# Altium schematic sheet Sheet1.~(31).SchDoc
size A
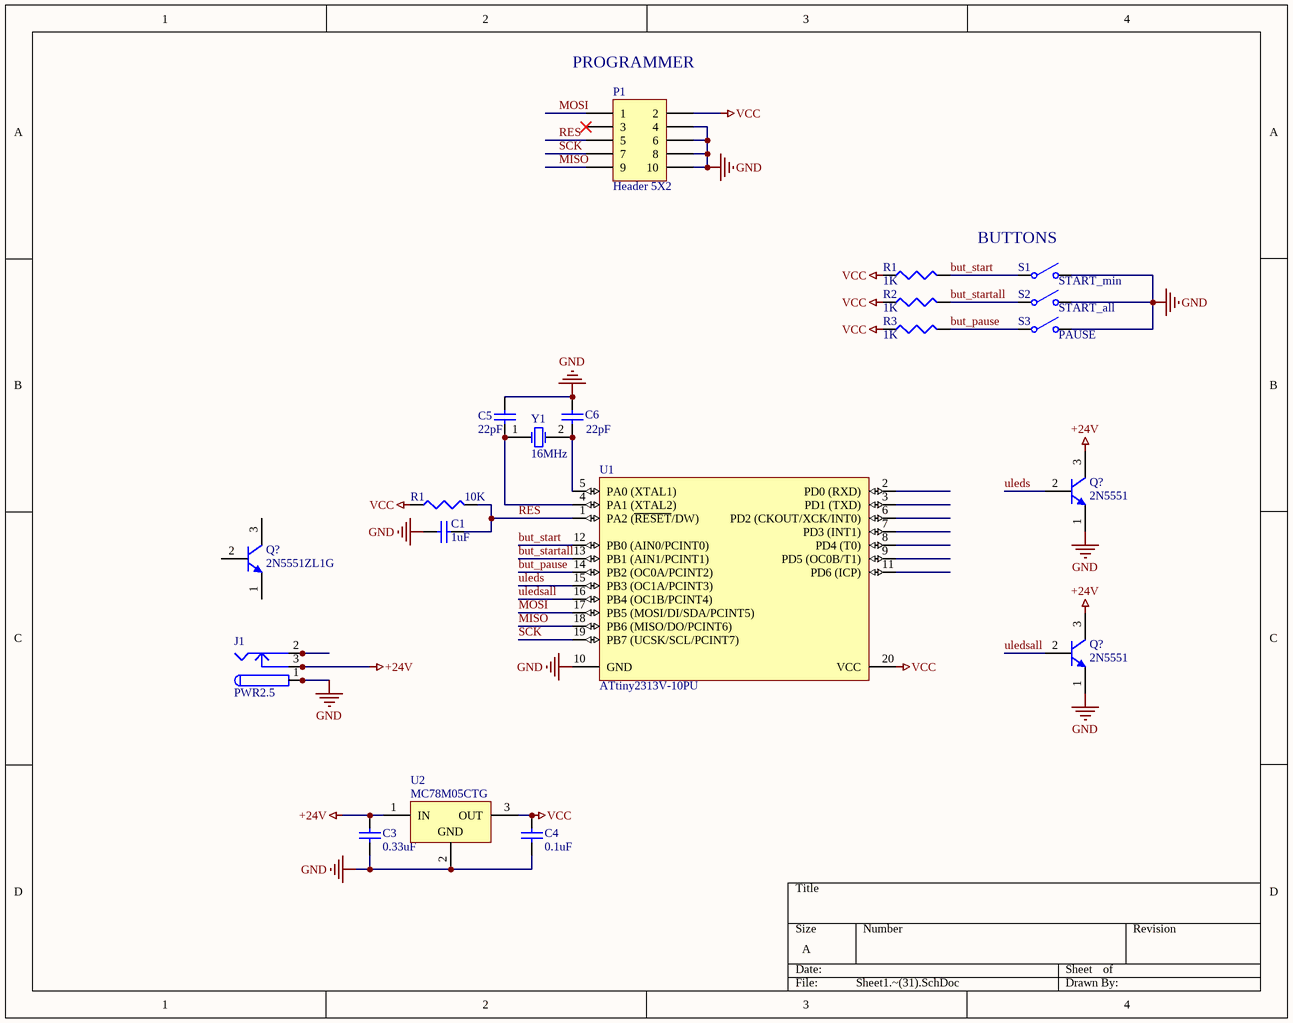
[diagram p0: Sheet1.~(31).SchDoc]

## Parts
(Parts that share a designator on the sheet are numbered #1, #2 ... from top to bottom, then left to right.)
C1  value 1uF  [1608[0603]]  (hidden comment: Cap Semi)
C3  value 0.33uF  [1608[0603]]  (hidden comment: Cap Semi)
C4  value 0.1uF  [1608[0603]]  (hidden comment: Cap Semi)
C5  value 22pF  [1608[0603]]  (hidden comment: Cap Semi)
C6  value 22pF  [1608[0603]]  (hidden comment: Cap Semi)
J1  PWR2.5  [KLD-0202]
P1  Header 5X2  [HDR2X5]
Q?#1  2N5551  [ONSC-TO-92-3-29-11_AM_BL]
Q?#2  2N5551ZL1G  [ONSC-TO-92-3-29-11_AM_BL]
Q?#3  2N5551  [ONSC-TO-92-3-29-11_AM_BL]
R1#1  value 1K  [J1-0603]  (hidden comment: Res3)
R1#2  value 10K  [J1-0603]  (hidden comment: Res3)
R2  value 1K  [J1-0603]  (hidden comment: Res3)
R3  value 1K  [J1-0603]  (hidden comment: Res3)
S1  START_min  [SPST-2]
S2  START_all  [SPST-2]
S3  PAUSE  [SPST-2]
U1  ATtiny2313V-10PU  [20P3]
U2  MC78M05CTG  [TO220]
Y1  16MHz  [HC-49U]

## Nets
+24V: C3.2 J1.3 J1.3A J1.3B Q?#1.3(C) Q?#3.3(C) U2.1(IN)
GND: C1.2 C3.1 C4.1 C5.1 C6.1 J1.1 J1.1A J1.1B P1.4 P1.6 P1.8 P1.10 Q?#1.1(E) Q?#3.1(E) S1.2(NO) S2.2(NO) S3.2(NO) U1.10(GND) U2.2(GND)
VCC: C4.2 P1.2 R1#1.1 R1#2.1 R2.1 R3.1 U1.20(VCC) U2.3(OUT)
but_pause: R3.2 S3.1(COMMON) U1.14(PB2_(OC0A/PCINT2))
but_start: R1#1.2 S1.1(COMMON) U1.12(PB0_(AIN0/PCINT0))
but_startall: R2.2 S2.1(COMMON) U1.13(PB1_(AIN1/PCINT1))
MISO: P1.9 U1.18(PB6_(MISO/DO/PCINT6))
MOSI: P1.1 U1.17(PB5_(MOSI/DI/SDA/PCINT5))
RES: C1.1 P1.5 R1#2.2 U1.1(PA2_(~{RESET}/DW))
SCK: P1.7 U1.19(PB7_(UCSK/SCL/PCINT7))
uleds: Q?#1.2(B) U1.15(PB3_(OC1A/PCINT3))
uledsall: Q?#3.2(B) U1.16(PB4_(OC1B/PCINT4))
NetC5_2: C5.2 U1.4(PA1_(XTAL2)) Y1.1(OSC1)
NetC6_2: C6.2 U1.5(PA0_(XTAL1)) Y1.2(OSC2)
NetJ1_2: J1.2 J1.2A J1.2B

Not connected (* = marked no-connect by the designer): P1 3*; Q?#2 1(E) 2(B) 3(C); U1 2(PD0_(RXD)) 3(PD1_(TXD)) 6(PD2_(CKOUT/XCK/INT0)) 7(PD3_(INT1)) 8(PD4_(T0)) 9(PD5_(OC0B/T1)) 11(PD6_(ICP))

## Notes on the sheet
- (near P1) PROGRAMMER
- (near S1) BUTTONS

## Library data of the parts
C1 C3-C6 = Cap Semi: Capacitor (Semiconductor SIM Model)
J1 = PWR2.5: Low Voltage Power Supply Connector
P1 = Header 5X2: Header, 5-Pin, Dual row
Q?#1 Q?#3 = CMP-1048-01479-1: Amplifier Transistor, NPN Silicon, 3-Pin TO-92, Pb-Free, Tape and Reel; PartNumber: 2N5551RL1G; Manufacturer: On Semiconductor; fT Min (MHz): 100; IC Continuous (A): 0.6
Q?#2 = CMP-1048-01489-1: Amplifier Transistor, NPN Silicon, 3-Pin TO-92, Pb-Free, Ammo Box; Manufacturer: On Semiconductor; fT Min (MHz): 100; IC Continuous (A): 0.6
R1#1 R1#2 R2 R3 = Res3: Resistor
S1-S3 = SW-SPST: Single-Pole, Single-Throw Switch
U1 = CMP-0093-00017-1: Low Power tinyAVR® 8-Bit Microcontroller, 2K Flash Memory, 10MHz, Industrial Temperature, 20-Lead PDIP, Pb-Free
U2 = CMP-0244-00483-1: Positive Voltage Regulator, 5V, 3-Pin TO-220
Y1 = XTAL: Crystal Oscillator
